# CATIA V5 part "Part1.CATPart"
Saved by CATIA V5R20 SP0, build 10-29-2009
Part number: Part1
Bounding box of the stored display mesh (mm): x -75 to 75, y -100 to 100, z 0 to 0
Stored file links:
  C:\Users\Lenovo\Desktop\存钱\Part1.CATPart
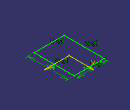
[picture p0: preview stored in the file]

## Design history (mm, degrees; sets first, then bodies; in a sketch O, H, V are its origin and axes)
Body1 (main body)
  Sketch1 on xy-plane, origin (0, 0, 0), H (1, 0, 0), V (0, 1, 0)
    line L1 (75, 100) -> (75, -100)
    line L2 (75, -100) -> (-75, -100)
    line L3 (-75, -100) -> (-75, 100)
    line L4 (-75, 100) -> (75, 100)
    length L4 = 150
    length L1 = 200
    vertical: L1 V, L3 V
    horizontal: L2 H, L4 H
    equidistance: L1 L3 O, L2 L4 O
  Pad1: profile Sketch1, direction (0, 0, 1), length 5
  Sketch2 on end face of Pad1, origin (0, 0, 5), H (1, 0, 0), V (0, 1, 0)
    point P1 (0, 75)
    line L1 (40, 90) -> (40, 60)
    line L2 (40, 60) -> (-40, 60)
    line L3 (-40, 60) -> (-40, 90)
    line L4 (-40, 90) -> (40, 90)
    reference projected line E1 (75, 100) -> (-75, 100) from edge [face of Pad1 from Sketch1.L4 | end face of Pad1]
    length L4 = 80
    length L1 = 30
    distance E1 L4 = 10
    coincidence: P1 V
    vertical: L1 V, L3 V
    horizontal: L2 H, L4 H
    equidistance: L1 L3 P1, L2 L4 P1
  Pocket1: profile Sketch2, direction (0, 0, -1), through (limit type 3)
  Sketch3 on end face of Pad1, origin (0, 0, 5), H (1, 0, 0), V (0, 1, 0)
    line L1 (-5, -10) -> (55, -10)
    line L2 (55, -10) -> (55, -50)
    line L3 (55, -50) -> (-5, -50)
    line L4 (-5, -50) -> (-5, -10)
    reference projected line E1 (75, -100) -> (75, 100) from edge [face of Pad1 from Sketch1.L1 | end face of Pad1]
    reference projected line E2 (-75, -100) -> (75, -100) from edge [face of Pad1 from Sketch1.L2 | end face of Pad1]
    distance L2 E1 = 20
    distance L3 E2 = 50
    length L1 = 60
    length L2 = 40
    horizontal: L1 H, L3 H
    vertical: L2 V, L4 V
  Pocket2: profile Sketch3, direction (0, 0, -1), through (limit type 3)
